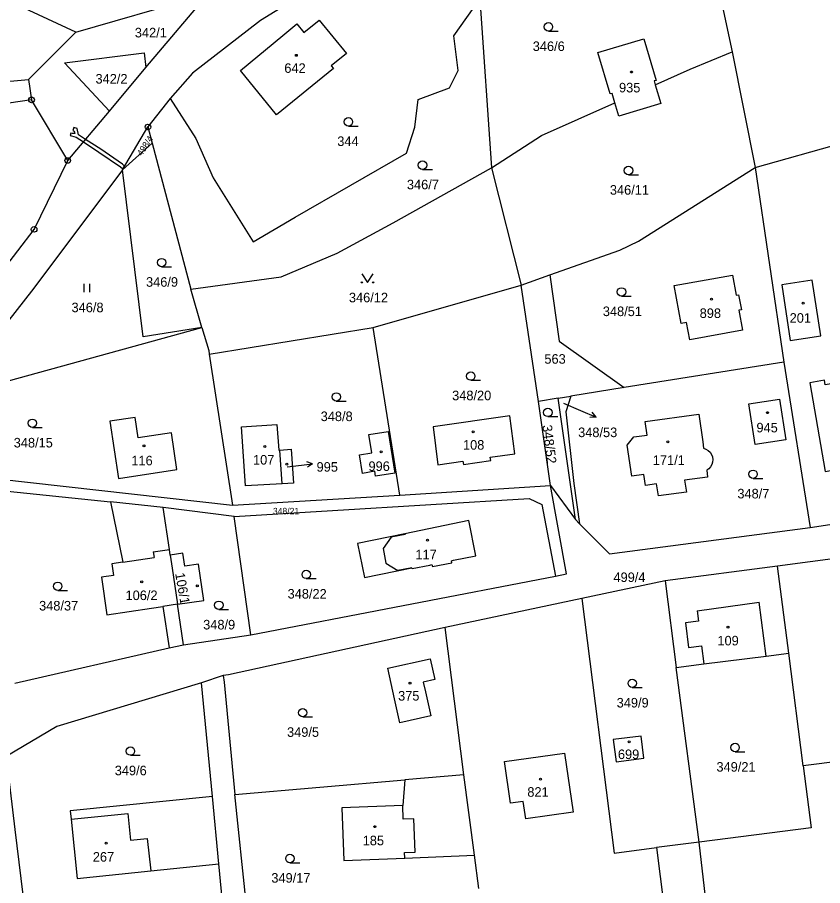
# Model space of a CAD drawing. Extents: x -725728 to -720881, y -1068679 to -1063504.
# Drawn here: x -724380.5 to -724237.4, y -1066956.8 to -1066802.4 of the extents above; entities that cross this region are included whole.
import ezdxf

# ---------------------------------------------------------------- set-up
doc = ezdxf.new("R2010")
doc.units = 0
for name, color, linetype in [('Hranice parcel', 7, 'Continuous'), ('Parcelní čísla', 7, 'Continuous'), ('Pop  PČ popisy', 7, 'Continuous'), ('Vnitřní kresba', 7, 'Continuous'), ('Věcná břemena k části', 7, 'Continuous'), ('Značky bodu BP', 7, 'Continuous'), ('Značky budov', 7, 'Continuous'), ('Značky kultur', 7, 'Continuous')]:
    doc.layers.add(name, color=color, linetype=linetype)

# ---------------------------------------------------------------- blocks, each defined once
blk = doc.blocks.new('4.02_4')
at = {"layer": 'Značky budov'}
blk.add_circle((-0.001, 0), 0.0175, dxfattribs=at)
blk = doc.blocks.new('4.02_3')
at = {"layer": 'Značky budov'}
blk.add_circle((-0.001, 0), 0.0175, dxfattribs=at)
blk = doc.blocks.new('1029_117')
at = {"layer": 'Pop  PČ popisy'}
for p, q in [((0, 0), (0.276, -0.117)), ((0.276, -0.117), (0.164, -0.124)), ((0.276, -0.117), (0.204, -0.032))]:
    blk.add_line(p, q, dxfattribs=at)
blk = doc.blocks.new('1029_118')
at = {"layer": 'Pop  PČ popisy'}
for p, q in [((0, 0), (0.298, 0.037)), ((0.298, 0.037), (0.192, 0.074)), ((0.298, 0.037), (0.205, -0.025))]:
    blk.add_line(p, q, dxfattribs=at)
blk = doc.blocks.new('3.04_2')
at = {"layer": 'Značky kultur'}
blk.add_line((0.001, 0), (0.176, 0), dxfattribs=at)
blk.add_circle((0.001, 0.075), 0.075, dxfattribs=at)
blk = doc.blocks.new('3.04_3')
at = {"layer": 'Značky kultur'}
blk.add_line((0.001, 0), (0.176, 0), dxfattribs=at)
blk.add_circle((0.001, 0.075), 0.075, dxfattribs=at)
blk = doc.blocks.new('3.06_1')
at = {"layer": 'Značky kultur'}
for p, q in [((-0.051, 0), (-0.051, 0.15)), ((0.049, 0), (0.049, 0.15))]:
    blk.add_line(p, q, dxfattribs=at)
blk = doc.blocks.new('3.14_1')
at = {"layer": 'Značky kultur'}
blk.add_lwpolyline([(-0.1, 0.15), (0, 0), (0.1, 0.15)], dxfattribs=at)
for centre in [(-0.1, 0), (0.1, 0)]:
    blk.add_circle(centre, 0.01, dxfattribs=at)
blk = doc.blocks.new('1.05_2')
at = {"layer": 'Značky bodu BP'}
for radius in [0.05, 0.00303]:
    blk.add_circle((0, 0), radius, dxfattribs=at)
blk = doc.blocks.new('1.05_1')
at = {"layer": 'Značky bodu BP'}
for radius in [0.05, 0.00303]:
    blk.add_circle((0, 0), radius, dxfattribs=at)

msp = doc.modelspace()

# ---------------------------------------------------------------- linework, layer by layer
at = {"layer": 'Hranice parcel'}
for p, q in [((-724259.27, -1066781.27), (-724253.49, -1066808.6)), ((-724370.14, -1066805.08), (-724399.29, -1066791.48)), ((-724370.14, -1066805.08), (-724346.64, -1066798.27)), ((-724357.68, -1066811.38), (-724346.64, -1066798.27)), ((-724298.34, -1066799.14), (-724296.25, -1066829.18)), ((-724378.57, -1066813.49), (-724370.14, -1066805.08)), ((-724253.49, -1066808.6), (-724249.35, -1066829.17)), ((-724364.18, -1066819.11), (-724357.68, -1066811.38)), ((-724378.57, -1066813.49), (-724378.02, -1066817.12)), ((-724267.34, -1066813.75), (-724267.14, -1066814.44)), ((-724267.14, -1066814.44), (-724266.16, -1066817.75)), ((-724274.32, -1066817.64), (-724274.81, -1066815.97)), ((-724378.02, -1066817.12), (-724402.91, -1066820.81)), ((-724371.59, -1066827.9), (-724378.02, -1066817.12)), ((-724353.39, -1066816.86), (-724357.33, -1066821.93)), ((-724273.61, -1066820), (-724274.32, -1066817.64)), ((-724266.16, -1066817.75), (-724273.61, -1066820)), ((-724371.59, -1066827.9), (-724364.18, -1066819.11)), ((-724361.86, -1066829.53), (-724357.33, -1066821.93)), ((-724357.33, -1066821.93), (-724356.57, -1066824.81)), ((-724356.57, -1066824.81), (-724361.86, -1066829.53)), ((-724356.57, -1066824.81), (-724349.72, -1066850.8)), ((-724249.35, -1066829.17), (-724232.23, -1066824.31)), ((-724296.25, -1066829.18), (-724290.98, -1066850.04)), ((-724249.35, -1066829.17), (-724244.31, -1066863.75)), ((-724290.98, -1066850.04), (-724285.88, -1066848.25)), ((-724317.31, -1066857.62), (-724290.98, -1066850.04)), ((-724287.87, -1066870.73), (-724290.98, -1066850.04)), ((-724347.74, -1066857.59), (-724349.72, -1066850.8)), ((-724346.43, -1066862.34), (-724317.31, -1066857.62)), ((-724312.53, -1066887.4), (-724317.31, -1066857.62)), ((-724346.43, -1066862.34), (-724342.28, -1066889.18)), ((-724244.31, -1066863.75), (-724272.65, -1066868.27)), ((-724244.31, -1066863.75), (-724239.61, -1066893.15)), ((-724272.65, -1066868.27), (-724282.14, -1066869.8)), ((-724284.41, -1066870.17), (-724287.87, -1066870.73)), ((-724284.41, -1066870.17), (-724282.14, -1066869.8)), ((-724281.34, -1066891.74), (-724284.41, -1066870.17)), ((-724285.75, -1066885.72), (-724287.87, -1066870.73)), ((-724333.45, -1066885.39), (-724333.86, -1066879.39)), ((-724312.53, -1066887.4), (-724285.75, -1066885.72)), ((-724285.75, -1066885.72), (-724281.34, -1066891.74)), ((-724384.05, -1066886.51), (-724363.99, -1066888.62)), ((-724342.28, -1066889.18), (-724312.53, -1066887.4)), ((-724354.61, -1066889.61), (-724363.99, -1066888.62)), ((-724341.99, -1066891.23), (-724354.61, -1066889.61)), ((-724239.61, -1066893.15), (-724216.61, -1066889.55)), ((-724339.03, -1066912.27), (-724341.99, -1066891.23)), ((-724280.58, -1066892.5), (-724281.34, -1066891.74)), ((-724222.91, -1066897.06), (-724245.39, -1066900.01)), ((-724245.39, -1066900.01), (-724265.4, -1066902.62)), ((-724243.4, -1066915.51), (-724245.39, -1066900.01)), ((-724339.03, -1066912.27), (-724284.89, -1066901.79)), ((-724265.4, -1066902.62), (-724280.22, -1066905.77)), ((-724265.4, -1066902.62), (-724263.4, -1066918.04)), ((-724280.22, -1066905.77), (-724304.51, -1066910.92)), ((-724350.99, -1066914), (-724352.05, -1066906.81)), ((-724301.15, -1066937.16), (-724304.51, -1066910.92)), ((-724350.99, -1066914), (-724339.03, -1066912.27)), ((-724380.97, -1066920.82), (-724353.55, -1066914.58)), ((-724353.55, -1066914.58), (-724350.99, -1066914)), ((-724240.82, -1066935.56), (-724243.4, -1066915.51)), ((-724259.36, -1066949.12), (-724263.4, -1066918.04)), ((-724343.94, -1066919.47), (-724347.81, -1066920.78)), ((-724345.87, -1066940.98), (-724347.81, -1066920.78)), ((-724230.86, -1066934.25), (-724240.82, -1066935.56)), ((-724341.89, -1066940.63), (-724311.64, -1066938.05)), ((-724301.15, -1066937.16), (-724311.64, -1066938.05)), ((-724299.27, -1066951.45), (-724301.15, -1066937.16)), ((-724344.71, -1066952.98), (-724345.87, -1066940.98)), ((-724339.48, -1066963.64), (-724341.89, -1066940.63)), ((-724259.36, -1066949.12), (-724266.89, -1066950.08)), ((-724252.63, -1067005.13), (-724259.36, -1066949.12)), ((-724298.49, -1066957.35), (-724299.27, -1066951.45))]:
    msp.add_line(p, q, dxfattribs=at)
for points in [[(-724310.29, -1066792.93), (-724319.2, -1066793.79), (-724326.12, -1066796.05), (-724337.31, -1066802.99), (-724349.4, -1066812.36), (-724353.39, -1066816.86)], [(-724353.39, -1066816.86), (-724348.8, -1066823.98), (-724345.75, -1066830.97), (-724338.65, -1066842.39), (-724331.17, -1066837.96), (-724311.37, -1066826.62), (-724309.88, -1066822), (-724309.29, -1066817.03), (-724303.69, -1066814.99), (-724302.2, -1066811.87), (-724302.97, -1066805.73), (-724298.34, -1066799.14)], [(-724324.75, -1066811.08), (-724324.36, -1066811.56), (-724334.45, -1066819.78), (-724340.86, -1066811.91), (-724333.35, -1066805.65), (-724330.87, -1066803.57), (-724329.59, -1066805.14), (-724326.87, -1066802.93), (-724322.03, -1066808.87), (-724324.75, -1066811.08)], [(-724274.81, -1066815.97), (-724275.16, -1066816.07), (-724277.34, -1066808.69), (-724269.15, -1066806.28), (-724266.99, -1066813.65), (-724267.34, -1066813.75)], [(-724267.14, -1066814.44), (-724260.94, -1066811.67), (-724253.49, -1066808.6)], [(-724364.18, -1066819.11), (-724372.18, -1066810.54), (-724358.02, -1066808.74), (-724357.68, -1066811.38)], [(-724419.79, -1066815.75), (-724402.97, -1066815.71), (-724378.57, -1066813.49)], [(-724296.25, -1066829.18), (-724287.38, -1066823.47), (-724274.32, -1066817.64)], [(-724405.4, -1066861.04), (-724389.22, -1066855.35), (-724377.57, -1066840.15), (-724371.59, -1066827.9)], [(-724361.86, -1066829.53), (-724377.64, -1066850.59), (-724389.94, -1066866.29)], [(-724347.74, -1066857.59), (-724358.16, -1066859.26), (-724361.86, -1066829.53)], [(-724349.72, -1066850.8), (-724333.62, -1066848.56), (-724323.7, -1066844.35), (-724313.74, -1066839.01), (-724296.25, -1066829.18)], [(-724285.88, -1066848.25), (-724273.41, -1066843.86), (-724270.12, -1066842.26), (-724249.35, -1066829.17)], [(-724285.88, -1066848.25), (-724284.23, -1066860.01), (-724272.65, -1066868.27)], [(-724253.4, -1066848.27), (-724252.77, -1066851.86), (-724252.33, -1066851.78), (-724251.83, -1066854.48), (-724252.27, -1066854.53), (-724251.62, -1066858.08), (-724261.02, -1066859.77), (-724261.56, -1066856.73), (-724262.55, -1066856.9), (-724263.78, -1066850.15), (-724253.4, -1066848.27)], [(-724243.15, -1066859.9), (-724237.72, -1066859.07), (-724239.22, -1066849.18), (-724244.66, -1066850.01), (-724243.15, -1066859.9)], [(-724389.94, -1066866.29), (-724389.27, -1066869.02), (-724347.74, -1066857.59)], [(-724347.74, -1066857.59), (-724346.53, -1066861.71), (-724346.43, -1066862.34)], [(-724230.15, -1066882), (-724232.74, -1066867.09), (-724236.92, -1066867.82), (-724237.06, -1066866.99), (-724239.68, -1066867.45), (-724236.94, -1066883.23), (-724230.15, -1066882)], [(-724282.14, -1066869.8), (-724283.05, -1066872.58), (-724281.59, -1066885.32), (-724280.58, -1066892.5)], [(-724245.03, -1066870.33), (-724243.92, -1066877.56), (-724249.36, -1066878.41), (-724250.49, -1066871.17), (-724245.03, -1066870.33)], [(-724306.62, -1066875.25), (-724305.77, -1066882), (-724301.34, -1066881.38), (-724301.24, -1066881.94), (-724296.38, -1066881.26), (-724296.47, -1066880.67), (-724292.12, -1066880.04), (-724292.99, -1066873.32), (-724306.62, -1066875.25)], [(-724258, -1066882.99), (-724257.84, -1066884.2), (-724261.92, -1066884.75), (-724261.6, -1066886.87), (-724266.56, -1066887.52), (-724266.89, -1066885.4), (-724268.89, -1066885.68), (-724269.17, -1066883.74), (-724271.33, -1066884.05), (-724272.12, -1066878.55), (-724270.94, -1066877.03), (-724268.6, -1066876.74), (-724268.94, -1066874.31), (-724259.42, -1066873.01), (-724258.71, -1066877.95), (-724258.56, -1066879.07)], [(-724352.17, -1066882.82), (-724353.14, -1066876.3), (-724359.06, -1066877.19), (-724359.6, -1066873.58), (-724364.11, -1066874.25), (-724362.59, -1066884.43), (-724352.17, -1066882.82)], [(-724333.45, -1066885.39), (-724340, -1066885.74), (-724340.67, -1066875.24), (-724334.39, -1066874.85), (-724334.06, -1066879.41), (-724333.86, -1066879.39)], [(-724313.45, -1066883.51), (-724316.85, -1066884.05), (-724316.99, -1066883.17), (-724319.19, -1066883.56), (-724319.71, -1066880.25), (-724317.53, -1066879.88), (-724318.06, -1066876.63), (-724314.65, -1066876.07), (-724313.45, -1066883.51)], [(-724333.86, -1066879.39), (-724331.84, -1066879.24), (-724331.48, -1066885.28), (-724333.45, -1066885.39)], [(-724258.56, -1066879.07), (-724258.12, -1066879.22), (-724257.73, -1066879.46), (-724257.4, -1066879.78), (-724257.15, -1066880.16), (-724256.98, -1066880.59), (-724256.97, -1066880.63), (-724256.91, -1066881.08), (-724256.95, -1066881.54), (-724257.09, -1066881.98), (-724257.32, -1066882.38), (-724257.62, -1066882.72), (-724258, -1066882.99)], [(-724406, -1066886.8), (-724384.06, -1066884.5), (-724342.28, -1066889.18)], [(-724284.89, -1066901.79), (-724282.93, -1066901.41), (-724285.75, -1066885.72)], [(-724363.99, -1066888.62), (-724361.81, -1066899.33), (-724363.75, -1066899.61), (-724363.44, -1066901.69), (-724365.6, -1066902.01), (-724364.61, -1066908.67), (-724356.71, -1066907.5), (-724354.67, -1066907.2), (-724353.55, -1066914.58)], [(-724341.99, -1066891.23), (-724289.57, -1066888.03), (-724287.3, -1066889.1), (-724284.89, -1066901.79)], [(-724353.35, -1066898.07), (-724353.5, -1066897.06), (-724354.61, -1066889.61)], [(-724302.99, -1066899), (-724299.01, -1066898.2), (-724300.26, -1066891.94), (-724311.63, -1066894.26)], [(-724280.58, -1066892.5), (-724275.27, -1066897.83), (-724239.61, -1066893.15)], [(-724311.63, -1066894.26), (-724320.06, -1066896.03), (-724318.82, -1066902.07), (-724310.4, -1066900.33)], [(-724352.05, -1066906.81), (-724347.38, -1066906.12), (-724348.33, -1066899.67), (-724350.78, -1066900.05), (-724351.12, -1066897.74), (-724353.35, -1066898.07)], [(-724353.35, -1066898.07), (-724353, -1066900.39), (-724352.05, -1066906.81)], [(-724307.22, -1066899.84), (-724306.83, -1066899.76), (-724306.76, -1066900.11), (-724303.32, -1066899.42), (-724303.39, -1066899.07), (-724302.99, -1066899)], [(-724310.4, -1066900.33), (-724310.37, -1066900.47), (-724307.22, -1066899.84)], [(-724280.22, -1066905.77), (-724274.42, -1066951.05), (-724266.89, -1066950.08)], [(-724304.51, -1066910.92), (-724343.01, -1066919.38), (-724343.94, -1066919.47)], [(-724308.01, -1066922.37), (-724307.05, -1066926.68), (-724312.53, -1066927.92), (-724313.49, -1066923.61), (-724314.71, -1066918.16), (-724307.15, -1066916.49), (-724306.34, -1066920.21), (-724308.39, -1066920.66), (-724308.01, -1066922.37)], [(-724263.4, -1066918.04), (-724258.48, -1066917.42), (-724247.44, -1066916.02), (-724243.4, -1066915.51)], [(-724343.94, -1066919.47), (-724343.76, -1066920.66), (-724341.89, -1066940.63)], [(-724347.81, -1066920.78), (-724373.52, -1066928.53), (-724382.56, -1066933.86)], [(-724269.67, -1066930.25), (-724274.62, -1066930.89), (-724274.11, -1066934.81), (-724269.17, -1066934.17), (-724269.67, -1066930.25)], [(-724292.9, -1066942.18), (-724293.94, -1066934.79), (-724283.25, -1066933.3), (-724281.75, -1066943.76), (-724290.12, -1066944.95), (-724290.61, -1066941.86), (-724292.9, -1066942.18)], [(-724382.56, -1066933.86), (-724380.98, -1066946.86), (-724378.07, -1066970.58)], [(-724240.82, -1066935.56), (-724239.44, -1066946.58), (-724259.36, -1066949.12)], [(-724311.64, -1066938.05), (-724312.03, -1066942.58), (-724322.87, -1066943.02), (-724322.48, -1066952.39), (-724311.65, -1066951.95), (-724299.27, -1066951.45)], [(-724345.87, -1066940.98), (-724371.15, -1066943.56), (-724371, -1066945.05), (-724369.92, -1066955.59), (-724356.84, -1066954.24), (-724344.71, -1066952.98)], [(-724266.89, -1066950.08), (-724264.91, -1066966.01), (-724296.75, -1066971.04)], [(-724343.63, -1066964.33), (-724343.77, -1066962.83), (-724344.71, -1066952.98)]]:
    msp.add_lwpolyline(points, dxfattribs=at)
at = {"layer": 'Pop  PČ popisy'}
for p, q in [((-724283.47, -1066871.07), (-724280.42, -1066872.35)), ((-724332.59, -1066882.39), (-724331.03, -1066882.21))]:
    msp.add_line(p, q, dxfattribs=at)
at = {"layer": 'Vnitřní kresba'}
for p, q in [((-724314.1, -1066894.87), (-724315.53, -1066896.92)), ((-724311.6, -1066894.41), (-724314.1, -1066894.87)), ((-724311.63, -1066894.26), (-724311.6, -1066894.41)), ((-724356.38, -1066897.49), (-724353.5, -1066897.06)), ((-724356.38, -1066897.49), (-724356.23, -1066898.5)), ((-724315.53, -1066896.92), (-724315.05, -1066899.49)), ((-724361.81, -1066899.33), (-724356.23, -1066898.5)), ((-724315.05, -1066899.49), (-724312.89, -1066900.82)), ((-724310.4, -1066900.33), (-724312.89, -1066900.82)), ((-724352.05, -1066906.81), (-724354.67, -1066907.2)), ((-724259.66, -1066907.98), (-724248.66, -1066906.42)), ((-724247.44, -1066916.02), (-724248.66, -1066906.42)), ((-724259.66, -1066907.98), (-724259.43, -1066909.83)), ((-724259.43, -1066909.83), (-724261.78, -1066910.13)), ((-724261.78, -1066910.13), (-724261.22, -1066914.5)), ((-724261.22, -1066914.5), (-724258.89, -1066914.21)), ((-724258.89, -1066914.21), (-724258.48, -1066917.42)), ((-724311.93, -1066945.02), (-724312.03, -1066942.58)), ((-724371, -1066945.05), (-724360.92, -1066944.02)), ((-724360.92, -1066944.02), (-724360.42, -1066948.78)), ((-724310.08, -1066944.94), (-724311.93, -1066945.02)), ((-724309.84, -1066950.9), (-724310.08, -1066944.94)), ((-724360.42, -1066948.78), (-724357.44, -1066948.47)), ((-724357.44, -1066948.47), (-724356.84, -1066954.24)), ((-724311.69, -1066950.97), (-724309.84, -1066950.9)), ((-724311.65, -1066951.95), (-724311.69, -1066950.97))]:
    msp.add_line(p, q, dxfattribs=at)
at = {"layer": 'Věcná břemena k části'}
msp.add_lwpolyline([(-724361.48, -1066828.89), (-724361.86, -1066828.56), (-724365.73, -1066825.91), (-724368.43, -1066824.15), (-724369.69, -1066823.32), (-724369.9, -1066822.2), (-724370.5, -1066822.01), (-724370.66, -1066822.59), (-724370.42, -1066822.66), (-724370.34, -1066823.11), (-724370.79, -1066823.09), (-724371.03, -1066823.02), (-724371.17, -1066823.44), (-724370.94, -1066823.52), (-724370.08, -1066823.78), (-724368.81, -1066824.61), (-724366.03, -1066826.43), (-724362.21, -1066829.05), (-724361.77, -1066829.37)], close=True, dxfattribs=at)

# ---------------------------------------------------------------- block references
at = {"layer": 'Pop  PČ popisy', "xscale": 10, "yscale": 10}
for name, p in [('1029_117', (-724280.42, -1066872.35)), ('1029_118', (-724331.03, -1066882.21))]:
    msp.add_blockref(name, p, dxfattribs=at)
at = {"layer": 'Značky bodu BP', "xscale": 10, "yscale": 10}
for name, p in [('1.05_1', (-724378.02, -1066817.12)), ('1.05_2', (-724357.33, -1066821.93)), ('1.05_2', (-724371.59, -1066827.9)), ('1.05_2', (-724377.57, -1066840.15))]:
    msp.add_blockref(name, p, dxfattribs=at)
at = {"layer": 'Značky budov', "xscale": 10, "yscale": 10}
for name, p in [('4.02_3', (-724330.94, -1066809.2)), ('4.02_4', (-724271.36, -1066812.16)), ('4.02_3', (-724257.14, -1066852.56)), ('4.02_3', (-724240.84, -1066853.29)), ('4.02_3', (-724247.18, -1066872.74)), ('4.02_4', (-724299.5, -1066876.17)), ('4.02_4', (-724264.87, -1066877.92)), ('4.02_3', (-724358.02, -1066878.62)), ('4.02_3', (-724336.52, -1066878.77)), ('4.02_3', (-724315.84, -1066879.72)), ('4.02_4', (-724332.65, -1066881.88)), ('4.02_4', (-724307.6, -1066895.4)), ('4.02_3', (-724358.43, -1066902.84)), ('4.02_3', (-724348.54, -1066903.55)), ('4.02_3', (-724254.2, -1066910.87)), ('4.02_3', (-724310.73, -1066920.85)), ('4.02_3', (-724271.76, -1066931.29)), ('4.02_4', (-724287.55, -1066937.93)), ('4.02_3', (-724316.97, -1066946.36)), ('4.02_3', (-724364.76, -1066949.3))]:
    msp.add_blockref(name, p, dxfattribs=at)
at = {"layer": 'Značky kultur', "xscale": 10, "yscale": 10}
for name, p in [('3.04_3', (-724286.15, -1066804.88)), ('3.04_2', (-724321.7, -1066821.77)), ('3.04_2', (-724308.52, -1066829.48)), ('3.04_3', (-724271.9, -1066830.43)), ('3.04_2', (-724354.9, -1066846.8)), ('3.14_1', (-724318.3, -1066849.57)), ('3.06_1', (-724368.14, -1066851.33)), ('3.04_2', (-724273.16, -1066852.02)), ('3.04_2', (-724299.95, -1066866.98)), ('3.04_2', (-724323.85, -1066870.69)), ('3.04_2', (-724286.24, -1066873.45)), ('3.04_3', (-724377.89, -1066875.38)), ('3.04_2', (-724249.77, -1066884.44)), ('3.04_2', (-724329.2, -1066902.25)), ('3.04_2', (-724373.38, -1066904.37)), ('3.04_2', (-724344.74, -1066907.74)), ('3.04_2', (-724271.23, -1066921.62)), ('3.04_2', (-724329.83, -1066926.84)), ('3.04_3', (-724360.46, -1066933.67)), ('3.04_2', (-724252.96, -1066933.03)), ('3.04_2', (-724332.09, -1066952.77))]:
    msp.add_blockref(name, p, dxfattribs=at)

# ---------------------------------------------------------------- texts
at = {"layer": 'Parcelní čísla'}
for s, height, p in [('342/1', 1.7, (-724359.66, -1066806.01)), ('346/6', 1.7, (-724288.92, -1066808.43)), ('642', 1.7, (-724333.08, -1066812.32)), ('342/2', 1.7, (-724366.65, -1066814.22)), ('935', 1.7, (-724273.58, -1066815.79)), ('344', 1.7, (-724323.67, -1066825.32)), ('346/7', 1.7, (-724311.29, -1066833.03)), ('346/11', 1.7, (-724275.21, -1066833.98)), ('346/9', 1.7, (-724357.67, -1066850.35)), ('346/12', 1.7, (-724321.6, -1066853.12)), ('346/8', 1.7, (-724370.91, -1066854.88)), ('348/51', 1.7, (-724276.46, -1066855.57)), ('898', 1.7, (-724259.24, -1066855.9)), ('201', 1.7, (-724243.25, -1066856.75)), ('563', 1.7, (-724286.85, -1066864.04)), ('348/20', 1.7, (-724303.25, -1066870.53)), ('348/8', 1.7, (-724326.62, -1066874.24)), ('945', 1.7, (-724249.15, -1066876.25)), ('348/53', 1.7, (-724280.85, -1066877.09)), ('348/15', 1.7, (-724381.19, -1066878.93)), ('108', 1.7, (-724301.32, -1066879.32)), ('116', 1.7, (-724360.28, -1066882.11)), ('107', 1.7, (-724338.65, -1066881.97)), ('171/1', 1.7, (-724267.58, -1066882.03)), ('995', 1.7, (-724327.35, -1066883.24)), ('996', 1.7, (-724318.12, -1066883.11)), ('348/7', 1.7, (-724252.54, -1066887.99)), ('348/21', 1.14, (-724335.11, -1066890.81)), ('117', 1.7, (-724309.78, -1066898.82)), ('499/4', 1.7, (-724274.57, -1066902.86)), ('106/2', 1.7, (-724361.31, -1066906.07)), ('348/22', 1.7, (-724332.5, -1066905.8)), ('348/37', 1.7, (-724376.68, -1066907.92)), ('348/9', 1.7, (-724347.51, -1066911.29)), ('109', 1.7, (-724256.09, -1066914.13)), ('375', 1.7, (-724312.86, -1066923.94)), ('349/9', 1.7, (-724274, -1066925.17)), ('349/5', 1.7, (-724332.6, -1066930.39)), ('699', 1.7, (-724273.78, -1066934.34)), ('349/21', 1.7, (-724256.26, -1066936.58)), ('349/6', 1.7, (-724363.23, -1066937.22)), ('821', 1.7, (-724289.88, -1066941.04)), ('185', 1.7, (-724319.15, -1066949.67)), ('267', 1.7, (-724367.13, -1066952.58)), ('349/17', 1.7, (-724335.39, -1066956.32))]:
    msp.add_text(s, height=height, dxfattribs=at).set_placement(p)
for s, height, rotation, p in [('498/4', 1.14, 57, (-724358.41, -1066827.18)), ('348/52', 1.7, 277, (-724287.21, -1066875.01)), ('106/1', 1.7, 280, (-724352.5, -1066901.35))]:
    msp.add_text(s, height=height, rotation=rotation, dxfattribs=at).set_placement(p)

doc.saveas('drawing.dxf')
